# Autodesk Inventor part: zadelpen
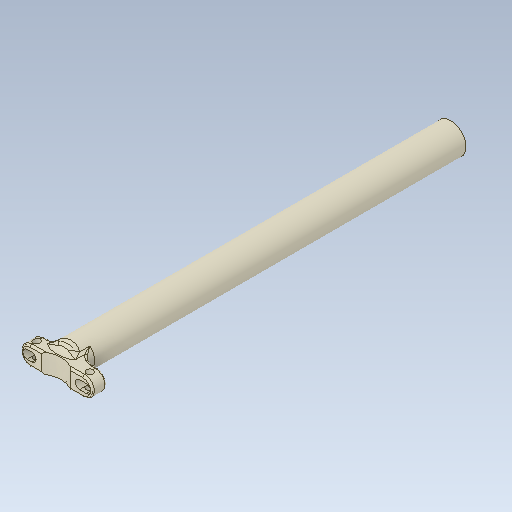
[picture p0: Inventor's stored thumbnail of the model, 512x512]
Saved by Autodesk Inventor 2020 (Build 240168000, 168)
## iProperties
Created: 2017-11
Part Number: zadelpen
Material: Ogólny
Document SubType Name: Modeling
Designer: Tomasz
Density: 1 g/cm^3
Appearance: Domyślna
Author: Tomasz
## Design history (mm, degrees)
feature "Solid1"
node "Bryła1"
